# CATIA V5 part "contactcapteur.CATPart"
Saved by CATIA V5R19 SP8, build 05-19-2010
Part number: contactcapteur
Revision: ANY
Definition: UNKNOWN
Nomenclature: contactcapteur
Source: Unknown
Bounding box of the stored display mesh (mm): x -0.5 to 0.5, y -1.4 to 1.4, z 0 to 4.5
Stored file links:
  D:\Documents\1_Travail\1 - ac-limoges.fr\ac-limoges.fr\Emmanuel Maynard - STI2D_Turgot\2 -2I2D\2_SEQUENCE_Serrure_Biométrique\5-Spé_ITEC\Serrure_Bio_Eleve\contactcapteur.CATPart
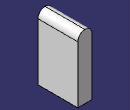
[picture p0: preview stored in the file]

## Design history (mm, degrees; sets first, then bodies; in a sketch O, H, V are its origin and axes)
Body1 "Base-Extrusion" (main body)
  Solid1: solid without history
